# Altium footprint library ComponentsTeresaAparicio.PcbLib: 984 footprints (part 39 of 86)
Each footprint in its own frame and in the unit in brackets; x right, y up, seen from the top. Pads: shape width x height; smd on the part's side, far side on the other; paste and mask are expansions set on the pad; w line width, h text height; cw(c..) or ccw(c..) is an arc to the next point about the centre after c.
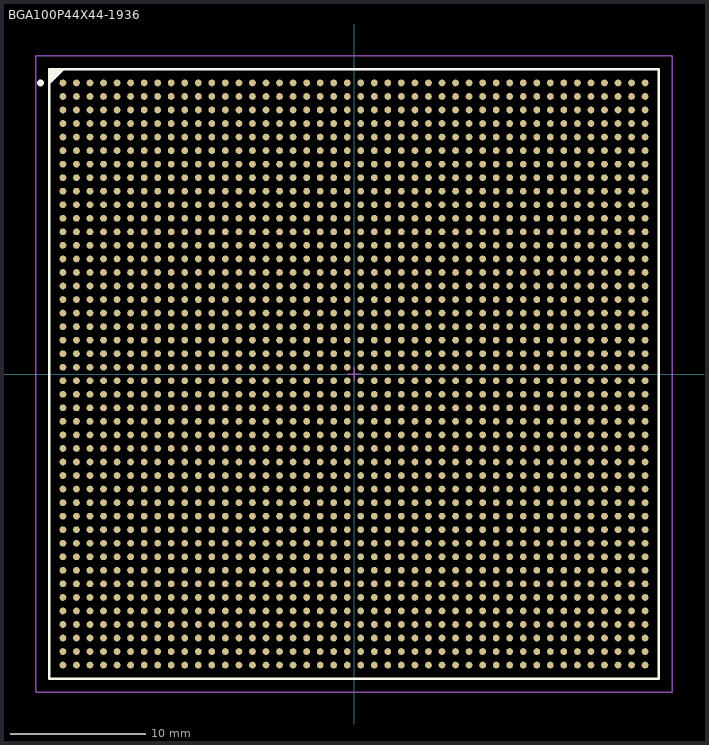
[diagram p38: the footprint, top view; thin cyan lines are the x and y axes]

## BGA100P44X44-1936 [mm] "BGA, 1936-Leads, Body 45x45mm, Pitch 1mm"
height 3.5
pads (1936):
  round 0.5 smd: A1(-21.5,21.5) A2(-20.5,21.5) A3(-19.5,21.5) A4(-18.5,21.5) A5(-17.5,21.5) A6(-16.5,21.5) A7(-15.5,21.5) A8(-14.5,21.5) A9(-13.5,21.5) A10(-12.5,21.5) A11(-11.5,21.5) A12(-10.5,21.5) A13(-9.5,21.5) A14(-8.5,21.5) A15(-7.5,21.5) A16(-6.5,21.5) A17(-5.5,21.5) A18(-4.5,21.5) A19(-3.5,21.5) A20(-2.5,21.5) A21(-1.5,21.5) A22(-0.5,21.5) A23(0.5,21.5) A24(1.5,21.5) A25(2.5,21.5) A26(3.5,21.5) A27(4.5,21.5) A28(5.5,21.5) A29(6.5,21.5) A30(7.5,21.5) A31(8.5,21.5) A32(9.5,21.5) A33(10.5,21.5) A34(11.5,21.5) A35(12.5,21.5) A36(13.5,21.5) A37(14.5,21.5) A38(15.5,21.5) A39(16.5,21.5) A40(17.5,21.5) A41(18.5,21.5) A42(19.5,21.5) A43(20.5,21.5) A44(21.5,21.5) AA1(-21.5,1.5) AA2(-20.5,1.5) AA3(-19.5,1.5) AA4(-18.5,1.5) AA5(-17.5,1.5) AA6(-16.5,1.5) AA7(-15.5,1.5) AA8(-14.5,1.5) AA9(-13.5,1.5) AA10(-12.5,1.5) AA11(-11.5,1.5) AA12(-10.5,1.5) AA13(-9.5,1.5) AA14(-8.5,1.5) AA15(-7.5,1.5) AA16(-6.5,1.5) AA17(-5.5,1.5) AA18(-4.5,1.5) AA19(-3.5,1.5) AA20(-2.5,1.5) AA21(-1.5,1.5) AA22(-0.5,1.5) AA23(0.5,1.5) AA24(1.5,1.5) AA25(2.5,1.5) AA26(3.5,1.5) AA27(4.5,1.5) AA28(5.5,1.5) AA29(6.5,1.5) AA30(7.5,1.5) AA31(8.5,1.5) AA32(9.5,1.5) AA33(10.5,1.5) AA34(11.5,1.5) AA35(12.5,1.5) AA36(13.5,1.5) AA37(14.5,1.5) AA38(15.5,1.5) AA39(16.5,1.5) AA40(17.5,1.5) AA41(18.5,1.5) AA42(19.5,1.5) AA43(20.5,1.5) AA44(21.5,1.5) AB1(-21.5,0.5) AB2(-20.5,0.5) AB3(-19.5,0.5) AB4(-18.5,0.5) AB5(-17.5,0.5) AB6(-16.5,0.5) AB7(-15.5,0.5) AB8(-14.5,0.5) AB9(-13.5,0.5) AB10(-12.5,0.5) AB11(-11.5,0.5) AB12(-10.5,0.5) AB13(-9.5,0.5) AB14(-8.5,0.5) AB15(-7.5,0.5) AB16(-6.5,0.5) AB17(-5.5,0.5) AB18(-4.5,0.5) AB19(-3.5,0.5) AB20(-2.5,0.5) AB21(-1.5,0.5) AB22(-0.5,0.5) AB23(0.5,0.5) AB24(1.5,0.5) AB25(2.5,0.5) AB26(3.5,0.5) AB27(4.5,0.5) AB28(5.5,0.5) AB29(6.5,0.5) AB30(7.5,0.5) AB31(8.5,0.5) AB32(9.5,0.5) AB33(10.5,0.5) AB34(11.5,0.5) AB35(12.5,0.5) AB36(13.5,0.5) AB37(14.5,0.5) AB38(15.5,0.5) AB39(16.5,0.5) AB40(17.5,0.5) AB41(18.5,0.5) AB42(19.5,0.5) AB43(20.5,0.5) AB44(21.5,0.5) AC1(-21.5,-0.5) AC2(-20.5,-0.5) AC3(-19.5,-0.5) AC4(-18.5,-0.5) AC5(-17.5,-0.5) AC6(-16.5,-0.5) AC7(-15.5,-0.5) AC8(-14.5,-0.5) AC9(-13.5,-0.5) AC10(-12.5,-0.5) AC11(-11.5,-0.5) AC12(-10.5,-0.5) AC13(-9.5,-0.5) AC14(-8.5,-0.5) AC15(-7.5,-0.5) AC16(-6.5,-0.5) AC17(-5.5,-0.5) AC18(-4.5,-0.5) AC19(-3.5,-0.5) AC20(-2.5,-0.5) AC21(-1.5,-0.5) AC22(-0.5,-0.5) AC23(0.5,-0.5) AC24(1.5,-0.5) AC25(2.5,-0.5) AC26(3.5,-0.5) AC27(4.5,-0.5) AC28(5.5,-0.5) AC29(6.5,-0.5) AC30(7.5,-0.5) AC31(8.5,-0.5) AC32(9.5,-0.5) AC33(10.5,-0.5) AC34(11.5,-0.5) AC35(12.5,-0.5) AC36(13.5,-0.5) AC37(14.5,-0.5) AC38(15.5,-0.5) AC39(16.5,-0.5) AC40(17.5,-0.5) AC41(18.5,-0.5) AC42(19.5,-0.5) AC43(20.5,-0.5) AC44(21.5,-0.5) AD1(-21.5,-1.5) AD2(-20.5,-1.5) AD3(-19.5,-1.5) AD4(-18.5,-1.5) AD5(-17.5,-1.5) AD6(-16.5,-1.5) AD7(-15.5,-1.5) AD8(-14.5,-1.5) AD9(-13.5,-1.5) AD10(-12.5,-1.5) AD11(-11.5,-1.5) AD12(-10.5,-1.5) AD13(-9.5,-1.5) AD14(-8.5,-1.5) AD15(-7.5,-1.5) AD16(-6.5,-1.5) AD17(-5.5,-1.5) AD18(-4.5,-1.5) AD19(-3.5,-1.5) AD20(-2.5,-1.5) AD21(-1.5,-1.5) AD22(-0.5,-1.5) AD23(0.5,-1.5) AD24(1.5,-1.5) AD25(2.5,-1.5) AD26(3.5,-1.5) AD27(4.5,-1.5) AD28(5.5,-1.5) AD29(6.5,-1.5) AD30(7.5,-1.5) AD31(8.5,-1.5) AD32(9.5,-1.5) AD33(10.5,-1.5) AD34(11.5,-1.5) AD35(12.5,-1.5) AD36(13.5,-1.5) AD37(14.5,-1.5) AD38(15.5,-1.5) AD39(16.5,-1.5) AD40(17.5,-1.5) AD41(18.5,-1.5) AD42(19.5,-1.5) AD43(20.5,-1.5) AD44(21.5,-1.5) AE1(-21.5,-2.5) AE2(-20.5,-2.5) AE3(-19.5,-2.5) AE4(-18.5,-2.5) AE5(-17.5,-2.5) AE6(-16.5,-2.5) AE7(-15.5,-2.5) AE8(-14.5,-2.5) AE9(-13.5,-2.5) AE10(-12.5,-2.5) AE11(-11.5,-2.5) AE12(-10.5,-2.5) AE13(-9.5,-2.5) AE14(-8.5,-2.5) AE15(-7.5,-2.5) AE16(-6.5,-2.5) AE17(-5.5,-2.5) AE18(-4.5,-2.5) AE19(-3.5,-2.5) AE20(-2.5,-2.5) AE21(-1.5,-2.5) AE22(-0.5,-2.5) AE23(0.5,-2.5) AE24(1.5,-2.5) AE25(2.5,-2.5) AE26(3.5,-2.5) AE27(4.5,-2.5) AE28(5.5,-2.5) AE29(6.5,-2.5) AE30(7.5,-2.5) AE31(8.5,-2.5) AE32(9.5,-2.5) AE33(10.5,-2.5) AE34(11.5,-2.5) AE35(12.5,-2.5) AE36(13.5,-2.5) AE37(14.5,-2.5) AE38(15.5,-2.5) AE39(16.5,-2.5) AE40(17.5,-2.5) AE41(18.5,-2.5) AE42(19.5,-2.5) AE43(20.5,-2.5) AE44(21.5,-2.5) AF1(-21.5,-3.5) AF2(-20.5,-3.5) AF3(-19.5,-3.5) AF4(-18.5,-3.5) AF5(-17.5,-3.5) AF6(-16.5,-3.5) AF7(-15.5,-3.5) AF8(-14.5,-3.5) AF9(-13.5,-3.5) AF10(-12.5,-3.5) AF11(-11.5,-3.5) AF12(-10.5,-3.5) AF13(-9.5,-3.5) AF14(-8.5,-3.5) AF15(-7.5,-3.5) AF16(-6.5,-3.5) AF17(-5.5,-3.5) AF18(-4.5,-3.5) AF19(-3.5,-3.5) AF20(-2.5,-3.5) AF21(-1.5,-3.5) AF22(-0.5,-3.5) AF23(0.5,-3.5) AF24(1.5,-3.5) AF25(2.5,-3.5) AF26(3.5,-3.5) AF27(4.5,-3.5) AF28(5.5,-3.5) AF29(6.5,-3.5) AF30(7.5,-3.5) AF31(8.5,-3.5) AF32(9.5,-3.5) AF33(10.5,-3.5) AF34(11.5,-3.5) AF35(12.5,-3.5) AF36(13.5,-3.5) AF37(14.5,-3.5) AF38(15.5,-3.5) AF39(16.5,-3.5) AF40(17.5,-3.5) AF41(18.5,-3.5) AF42(19.5,-3.5) AF43(20.5,-3.5) AF44(21.5,-3.5) AG1(-21.5,-4.5) AG2(-20.5,-4.5) AG3(-19.5,-4.5) AG4(-18.5,-4.5) AG5(-17.5,-4.5) AG6(-16.5,-4.5) AG7(-15.5,-4.5) AG8(-14.5,-4.5) AG9(-13.5,-4.5) AG10(-12.5,-4.5) AG11(-11.5,-4.5) AG12(-10.5,-4.5) AG13(-9.5,-4.5) AG14(-8.5,-4.5) AG15(-7.5,-4.5) AG16(-6.5,-4.5) AG17(-5.5,-4.5) AG18(-4.5,-4.5) AG19(-3.5,-4.5) AG20(-2.5,-4.5) AG21(-1.5,-4.5) AG22(-0.5,-4.5) AG23(0.5,-4.5) AG24(1.5,-4.5) AG25(2.5,-4.5) AG26(3.5,-4.5) AG27(4.5,-4.5) AG28(5.5,-4.5) AG29(6.5,-4.5) AG30(7.5,-4.5) AG31(8.5,-4.5) AG32(9.5,-4.5) AG33(10.5,-4.5) AG34(11.5,-4.5) AG35(12.5,-4.5) AG36(13.5,-4.5) AG37(14.5,-4.5) AG38(15.5,-4.5) AG39(16.5,-4.5) AG40(17.5,-4.5) AG41(18.5,-4.5) AG42(19.5,-4.5) AG43(20.5,-4.5) AG44(21.5,-4.5) AH1(-21.5,-5.5) AH2(-20.5,-5.5) AH3(-19.5,-5.5) AH4(-18.5,-5.5) AH5(-17.5,-5.5) AH6(-16.5,-5.5) AH7(-15.5,-5.5) AH8(-14.5,-5.5) AH9(-13.5,-5.5) AH10(-12.5,-5.5) AH11(-11.5,-5.5) AH12(-10.5,-5.5) AH13(-9.5,-5.5) AH14(-8.5,-5.5) AH15(-7.5,-5.5) AH16(-6.5,-5.5) AH17(-5.5,-5.5) AH18(-4.5,-5.5) AH19(-3.5,-5.5) AH20(-2.5,-5.5) AH21(-1.5,-5.5) AH22(-0.5,-5.5) AH23(0.5,-5.5) AH24(1.5,-5.5) AH25(2.5,-5.5) AH26(3.5,-5.5) AH27(4.5,-5.5) AH28(5.5,-5.5) AH29(6.5,-5.5) AH30(7.5,-5.5) AH31(8.5,-5.5) AH32(9.5,-5.5) AH33(10.5,-5.5) AH34(11.5,-5.5) AH35(12.5,-5.5) AH36(13.5,-5.5) AH37(14.5,-5.5) AH38(15.5,-5.5) AH39(16.5,-5.5) AH40(17.5,-5.5) AH41(18.5,-5.5) AH42(19.5,-5.5) AH43(20.5,-5.5) AH44(21.5,-5.5) AJ1(-21.5,-6.5) AJ2(-20.5,-6.5) AJ3(-19.5,-6.5) AJ4(-18.5,-6.5) AJ5(-17.5,-6.5) AJ6(-16.5,-6.5) AJ7(-15.5,-6.5) AJ8(-14.5,-6.5) AJ9(-13.5,-6.5) AJ10(-12.5,-6.5) AJ11(-11.5,-6.5) AJ12(-10.5,-6.5) AJ13(-9.5,-6.5) AJ14(-8.5,-6.5) AJ15(-7.5,-6.5) AJ16(-6.5,-6.5) AJ17(-5.5,-6.5) AJ18(-4.5,-6.5) AJ19(-3.5,-6.5) AJ20(-2.5,-6.5) AJ21(-1.5,-6.5) AJ22(-0.5,-6.5) AJ23(0.5,-6.5) AJ24(1.5,-6.5) AJ25(2.5,-6.5) AJ26(3.5,-6.5) AJ27(4.5,-6.5) AJ28(5.5,-6.5) AJ29(6.5,-6.5) AJ30(7.5,-6.5) AJ31(8.5,-6.5) AJ32(9.5,-6.5) AJ33(10.5,-6.5) AJ34(11.5,-6.5) AJ35(12.5,-6.5) AJ36(13.5,-6.5) AJ37(14.5,-6.5) AJ38(15.5,-6.5) AJ39(16.5,-6.5) AJ40(17.5,-6.5) AJ41(18.5,-6.5) AJ42(19.5,-6.5) AJ43(20.5,-6.5) AJ44(21.5,-6.5) AK1(-21.5,-7.5) AK2(-20.5,-7.5) AK3(-19.5,-7.5) AK4(-18.5,-7.5) AK5(-17.5,-7.5) AK6(-16.5,-7.5) AK7(-15.5,-7.5) AK8(-14.5,-7.5) AK9(-13.5,-7.5) AK10(-12.5,-7.5) AK11(-11.5,-7.5) AK12(-10.5,-7.5) AK13(-9.5,-7.5) AK14(-8.5,-7.5) AK15(-7.5,-7.5) AK16(-6.5,-7.5) AK17(-5.5,-7.5) AK18(-4.5,-7.5) AK19(-3.5,-7.5) AK20(-2.5,-7.5) AK21(-1.5,-7.5) AK22(-0.5,-7.5) AK23(0.5,-7.5) AK24(1.5,-7.5) AK25(2.5,-7.5) AK26(3.5,-7.5) AK27(4.5,-7.5) AK28(5.5,-7.5) AK29(6.5,-7.5) AK30(7.5,-7.5) AK31(8.5,-7.5) AK32(9.5,-7.5) AK33(10.5,-7.5) AK34(11.5,-7.5) AK35(12.5,-7.5) AK36(13.5,-7.5) AK37(14.5,-7.5) AK38(15.5,-7.5) AK39(16.5,-7.5) AK40(17.5,-7.5) AK41(18.5,-7.5) AK42(19.5,-7.5) AK43(20.5,-7.5) AK44(21.5,-7.5) AL1(-21.5,-8.5) AL2(-20.5,-8.5) AL3(-19.5,-8.5) AL4(-18.5,-8.5) AL5(-17.5,-8.5) AL6(-16.5,-8.5) AL7(-15.5,-8.5) AL8(-14.5,-8.5) AL9(-13.5,-8.5) AL10(-12.5,-8.5) AL11(-11.5,-8.5) AL12(-10.5,-8.5) AL13(-9.5,-8.5) AL14(-8.5,-8.5) AL15(-7.5,-8.5) AL16(-6.5,-8.5) AL17(-5.5,-8.5) AL18(-4.5,-8.5) AL19(-3.5,-8.5) AL20(-2.5,-8.5) AL21(-1.5,-8.5) AL22(-0.5,-8.5) AL23(0.5,-8.5) AL24(1.5,-8.5) AL25(2.5,-8.5) AL26(3.5,-8.5) AL27(4.5,-8.5) AL28(5.5,-8.5) AL29(6.5,-8.5) AL30(7.5,-8.5) AL31(8.5,-8.5) AL32(9.5,-8.5) AL33(10.5,-8.5) AL34(11.5,-8.5) AL35(12.5,-8.5) AL36(13.5,-8.5) AL37(14.5,-8.5) AL38(15.5,-8.5) AL39(16.5,-8.5) AL40(17.5,-8.5) AL41(18.5,-8.5) AL42(19.5,-8.5) AL43(20.5,-8.5) AL44(21.5,-8.5) AM1(-21.5,-9.5) AM2(-20.5,-9.5) AM3(-19.5,-9.5) AM4(-18.5,-9.5) AM5(-17.5,-9.5) AM6(-16.5,-9.5) AM7(-15.5,-9.5) AM8(-14.5,-9.5) AM9(-13.5,-9.5) AM10(-12.5,-9.5) AM11(-11.5,-9.5) AM12(-10.5,-9.5) AM13(-9.5,-9.5) AM14(-8.5,-9.5) AM15(-7.5,-9.5) AM16(-6.5,-9.5) AM17(-5.5,-9.5) AM18(-4.5,-9.5) AM19(-3.5,-9.5) AM20(-2.5,-9.5) AM21(-1.5,-9.5) AM22(-0.5,-9.5) AM23(0.5,-9.5) AM24(1.5,-9.5) AM25(2.5,-9.5) AM26(3.5,-9.5) AM27(4.5,-9.5) AM28(5.5,-9.5) AM29(6.5,-9.5) AM30(7.5,-9.5) AM31(8.5,-9.5) AM32(9.5,-9.5) AM33(10.5,-9.5) AM34(11.5,-9.5) AM35(12.5,-9.5) AM36(13.5,-9.5) AM37(14.5,-9.5) AM38(15.5,-9.5) AM39(16.5,-9.5) AM40(17.5,-9.5) AM41(18.5,-9.5) AM42(19.5,-9.5) AM43(20.5,-9.5) AM44(21.5,-9.5) AN1(-21.5,-10.5) AN2(-20.5,-10.5) AN3(-19.5,-10.5) AN4(-18.5,-10.5) AN5(-17.5,-10.5) AN6(-16.5,-10.5) AN7(-15.5,-10.5) AN8(-14.5,-10.5) AN9(-13.5,-10.5) AN10(-12.5,-10.5) AN11(-11.5,-10.5) AN12(-10.5,-10.5) AN13(-9.5,-10.5) AN14(-8.5,-10.5) AN15(-7.5,-10.5) AN16(-6.5,-10.5) AN17(-5.5,-10.5) AN18(-4.5,-10.5) AN19(-3.5,-10.5) AN20(-2.5,-10.5) AN21(-1.5,-10.5) AN22(-0.5,-10.5) AN23(0.5,-10.5) AN24(1.5,-10.5) AN25(2.5,-10.5) AN26(3.5,-10.5) AN27(4.5,-10.5) AN28(5.5,-10.5) AN29(6.5,-10.5) AN30(7.5,-10.5) AN31(8.5,-10.5) AN32(9.5,-10.5) AN33(10.5,-10.5) AN34(11.5,-10.5) AN35(12.5,-10.5) AN36(13.5,-10.5) AN37(14.5,-10.5) AN38(15.5,-10.5) AN39(16.5,-10.5) AN40(17.5,-10.5) AN41(18.5,-10.5) AN42(19.5,-10.5) AN43(20.5,-10.5) AN44(21.5,-10.5) AP1(-21.5,-11.5) AP2(-20.5,-11.5) AP3(-19.5,-11.5) AP4(-18.5,-11.5) AP5(-17.5,-11.5) AP6(-16.5,-11.5) AP7(-15.5,-11.5) AP8(-14.5,-11.5) AP9(-13.5,-11.5) AP10(-12.5,-11.5) AP11(-11.5,-11.5) AP12(-10.5,-11.5) AP13(-9.5,-11.5) AP14(-8.5,-11.5) AP15(-7.5,-11.5) AP16(-6.5,-11.5) AP17(-5.5,-11.5) AP18(-4.5,-11.5) AP19(-3.5,-11.5) AP20(-2.5,-11.5) AP21(-1.5,-11.5) AP22(-0.5,-11.5) AP23(0.5,-11.5) AP24(1.5,-11.5) AP25(2.5,-11.5) AP26(3.5,-11.5) AP27(4.5,-11.5) AP28(5.5,-11.5) AP29(6.5,-11.5) AP30(7.5,-11.5) AP31(8.5,-11.5) AP32(9.5,-11.5) AP33(10.5,-11.5) AP34(11.5,-11.5) AP35(12.5,-11.5) AP36(13.5,-11.5) AP37(14.5,-11.5) AP38(15.5,-11.5) AP39(16.5,-11.5) AP40(17.5,-11.5) AP41(18.5,-11.5) AP42(19.5,-11.5) AP43(20.5,-11.5) AP44(21.5,-11.5) AR1(-21.5,-12.5) AR2(-20.5,-12.5) AR3(-19.5,-12.5) AR4(-18.5,-12.5) AR5(-17.5,-12.5) AR6(-16.5,-12.5) AR7(-15.5,-12.5) AR8(-14.5,-12.5) AR9(-13.5,-12.5) AR10(-12.5,-12.5) AR11(-11.5,-12.5) AR12(-10.5,-12.5) AR13(-9.5,-12.5) AR14(-8.5,-12.5) AR15(-7.5,-12.5) AR16(-6.5,-12.5) AR17(-5.5,-12.5) AR18(-4.5,-12.5) AR19(-3.5,-12.5) AR20(-2.5,-12.5) AR21(-1.5,-12.5) AR22(-0.5,-12.5) AR23(0.5,-12.5) AR24(1.5,-12.5) AR25(2.5,-12.5) AR26(3.5,-12.5) AR27(4.5,-12.5) AR28(5.5,-12.5) AR29(6.5,-12.5) AR30(7.5,-12.5) AR31(8.5,-12.5) AR32(9.5,-12.5) AR33(10.5,-12.5) AR34(11.5,-12.5) AR35(12.5,-12.5) AR36(13.5,-12.5) AR37(14.5,-12.5) AR38(15.5,-12.5) AR39(16.5,-12.5) AR40(17.5,-12.5) AR41(18.5,-12.5) AR42(19.5,-12.5) AR43(20.5,-12.5) AR44(21.5,-12.5) AT1(-21.5,-13.5) AT2(-20.5,-13.5) AT3(-19.5,-13.5) AT4(-18.5,-13.5) AT5(-17.5,-13.5) AT6(-16.5,-13.5) AT7(-15.5,-13.5) AT8(-14.5,-13.5) AT9(-13.5,-13.5) AT10(-12.5,-13.5) AT11(-11.5,-13.5) AT12(-10.5,-13.5) AT13(-9.5,-13.5) AT14(-8.5,-13.5) AT15(-7.5,-13.5) AT16(-6.5,-13.5) AT17(-5.5,-13.5) AT18(-4.5,-13.5) AT19(-3.5,-13.5) AT20(-2.5,-13.5) AT21(-1.5,-13.5) AT22(-0.5,-13.5) AT23(0.5,-13.5) AT24(1.5,-13.5) AT25(2.5,-13.5) AT26(3.5,-13.5) AT27(4.5,-13.5) AT28(5.5,-13.5) AT29(6.5,-13.5) AT30(7.5,-13.5) AT31(8.5,-13.5) AT32(9.5,-13.5) AT33(10.5,-13.5) AT34(11.5,-13.5) AT35(12.5,-13.5) AT36(13.5,-13.5) AT37(14.5,-13.5) AT38(15.5,-13.5) AT39(16.5,-13.5) AT40(17.5,-13.5) AT41(18.5,-13.5) AT42(19.5,-13.5) AT43(20.5,-13.5) AT44(21.5,-13.5) AU1(-21.5,-14.5) AU2(-20.5,-14.5) AU3(-19.5,-14.5) AU4(-18.5,-14.5) AU5(-17.5,-14.5) AU6(-16.5,-14.5) AU7(-15.5,-14.5) AU8(-14.5,-14.5) AU9(-13.5,-14.5) AU10(-12.5,-14.5) AU11(-11.5,-14.5) AU12(-10.5,-14.5) AU13(-9.5,-14.5) AU14(-8.5,-14.5) AU15(-7.5,-14.5) AU16(-6.5,-14.5) AU17(-5.5,-14.5) AU18(-4.5,-14.5) AU19(-3.5,-14.5) AU20(-2.5,-14.5) AU21(-1.5,-14.5) AU22(-0.5,-14.5) AU23(0.5,-14.5) AU24(1.5,-14.5) AU25(2.5,-14.5) AU26(3.5,-14.5) AU27(4.5,-14.5) AU28(5.5,-14.5) AU29(6.5,-14.5) AU30(7.5,-14.5) AU31(8.5,-14.5) AU32(9.5,-14.5) AU33(10.5,-14.5) AU34(11.5,-14.5) AU35(12.5,-14.5) AU36(13.5,-14.5) AU37(14.5,-14.5) AU38(15.5,-14.5) AU39(16.5,-14.5) AU40(17.5,-14.5) AU41(18.5,-14.5) AU42(19.5,-14.5) AU43(20.5,-14.5) AU44(21.5,-14.5) AV1(-21.5,-15.5) AV2(-20.5,-15.5) AV3(-19.5,-15.5) AV4(-18.5,-15.5) AV5(-17.5,-15.5) AV6(-16.5,-15.5) AV7(-15.5,-15.5) AV8(-14.5,-15.5) AV9(-13.5,-15.5) AV10(-12.5,-15.5) AV11(-11.5,-15.5) AV12(-10.5,-15.5) AV13(-9.5,-15.5) AV14(-8.5,-15.5) AV15(-7.5,-15.5) AV16(-6.5,-15.5) AV17(-5.5,-15.5) AV18(-4.5,-15.5) AV19(-3.5,-15.5) AV20(-2.5,-15.5) AV21(-1.5,-15.5) AV22(-0.5,-15.5) AV23(0.5,-15.5) AV24(1.5,-15.5) AV25(2.5,-15.5) AV26(3.5,-15.5) AV27(4.5,-15.5) AV28(5.5,-15.5) AV29(6.5,-15.5) AV30(7.5,-15.5) AV31(8.5,-15.5) AV32(9.5,-15.5) AV33(10.5,-15.5) AV34(11.5,-15.5) AV35(12.5,-15.5) AV36(13.5,-15.5) AV37(14.5,-15.5) AV38(15.5,-15.5) AV39(16.5,-15.5) AV40(17.5,-15.5) AV41(18.5,-15.5) AV42(19.5,-15.5) AV43(20.5,-15.5) AV44(21.5,-15.5) AW1(-21.5,-16.5) AW2(-20.5,-16.5) AW3(-19.5,-16.5) AW4(-18.5,-16.5) AW5(-17.5,-16.5) AW6(-16.5,-16.5) AW7(-15.5,-16.5) AW8(-14.5,-16.5) AW9(-13.5,-16.5) AW10(-12.5,-16.5) AW11(-11.5,-16.5) AW12(-10.5,-16.5) AW13(-9.5,-16.5) AW14(-8.5,-16.5) AW15(-7.5,-16.5) AW16(-6.5,-16.5) AW17(-5.5,-16.5) AW18(-4.5,-16.5) AW19(-3.5,-16.5) AW20(-2.5,-16.5) AW21(-1.5,-16.5) AW22(-0.5,-16.5) AW23(0.5,-16.5) AW24(1.5,-16.5) AW25(2.5,-16.5) AW26(3.5,-16.5) AW27(4.5,-16.5) AW28(5.5,-16.5) AW29(6.5,-16.5) AW30(7.5,-16.5) AW31(8.5,-16.5) AW32(9.5,-16.5) AW33(10.5,-16.5) AW34(11.5,-16.5) AW35(12.5,-16.5) AW36(13.5,-16.5) AW37(14.5,-16.5) AW38(15.5,-16.5) AW39(16.5,-16.5) AW40(17.5,-16.5) AW41(18.5,-16.5) AW42(19.5,-16.5) AW43(20.5,-16.5) AW44(21.5,-16.5) AY1(-21.5,-17.5) AY2(-20.5,-17.5) AY3(-19.5,-17.5) AY4(-18.5,-17.5) AY5(-17.5,-17.5) AY6(-16.5,-17.5) AY7(-15.5,-17.5) AY8(-14.5,-17.5) AY9(-13.5,-17.5) AY10(-12.5,-17.5) AY11(-11.5,-17.5) AY12(-10.5,-17.5) AY13(-9.5,-17.5) AY14(-8.5,-17.5) AY15(-7.5,-17.5) AY16(-6.5,-17.5) AY17(-5.5,-17.5) AY18(-4.5,-17.5) AY19(-3.5,-17.5) AY20(-2.5,-17.5) AY21(-1.5,-17.5) AY22(-0.5,-17.5) AY23(0.5,-17.5) AY24(1.5,-17.5) AY25(2.5,-17.5) AY26(3.5,-17.5) AY27(4.5,-17.5) AY28(5.5,-17.5) AY29(6.5,-17.5) AY30(7.5,-17.5) AY31(8.5,-17.5) AY32(9.5,-17.5) AY33(10.5,-17.5) AY34(11.5,-17.5) AY35(12.5,-17.5) AY36(13.5,-17.5) AY37(14.5,-17.5) AY38(15.5,-17.5) AY39(16.5,-17.5) AY40(17.5,-17.5) AY41(18.5,-17.5) AY42(19.5,-17.5) AY43(20.5,-17.5) AY44(21.5,-17.5) B1(-21.5,20.5) B2(-20.5,20.5) B3(-19.5,20.5) B4(-18.5,20.5) B5(-17.5,20.5) B6(-16.5,20.5) B7(-15.5,20.5) B8(-14.5,20.5) B9(-13.5,20.5) B10(-12.5,20.5) B11(-11.5,20.5) B12(-10.5,20.5) B13(-9.5,20.5) B14(-8.5,20.5) B15(-7.5,20.5) B16(-6.5,20.5) B17(-5.5,20.5) B18(-4.5,20.5) B19(-3.5,20.5) B20(-2.5,20.5) B21(-1.5,20.5) B22(-0.5,20.5) B23(0.5,20.5) B24(1.5,20.5) B25(2.5,20.5) B26(3.5,20.5) B27(4.5,20.5) B28(5.5,20.5) B29(6.5,20.5) B30(7.5,20.5) B31(8.5,20.5) B32(9.5,20.5) B33(10.5,20.5) B34(11.5,20.5) B35(12.5,20.5) B36(13.5,20.5) B37(14.5,20.5) B38(15.5,20.5) B39(16.5,20.5) B40(17.5,20.5) B41(18.5,20.5) B42(19.5,20.5) B43(20.5,20.5) B44(21.5,20.5) BA1(-21.5,-18.5) BA2(-20.5,-18.5) BA3(-19.5,-18.5) BA4(-18.5,-18.5) BA5(-17.5,-18.5) BA6(-16.5,-18.5) BA7(-15.5,-18.5) BA8(-14.5,-18.5) BA9(-13.5,-18.5) BA10(-12.5,-18.5) BA11(-11.5,-18.5) BA12(-10.5,-18.5) BA13(-9.5,-18.5) BA14(-8.5,-18.5) BA15(-7.5,-18.5) BA16(-6.5,-18.5) BA17(-5.5,-18.5) BA18(-4.5,-18.5) BA19(-3.5,-18.5) BA20(-2.5,-18.5) BA21(-1.5,-18.5) BA22(-0.5,-18.5) BA23(0.5,-18.5) BA24(1.5,-18.5) BA25(2.5,-18.5) BA26(3.5,-18.5) BA27(4.5,-18.5) BA28(5.5,-18.5) BA29(6.5,-18.5) BA30(7.5,-18.5) BA31(8.5,-18.5) BA32(9.5,-18.5) BA33(10.5,-18.5) BA34(11.5,-18.5) BA35(12.5,-18.5) BA36(13.5,-18.5) BA37(14.5,-18.5) BA38(15.5,-18.5) BA39(16.5,-18.5) BA40(17.5,-18.5) BA41(18.5,-18.5) BA42(19.5,-18.5) BA43(20.5,-18.5) BA44(21.5,-18.5) BB1(-21.5,-19.5) BB2(-20.5,-19.5) BB3(-19.5,-19.5) BB4(-18.5,-19.5) BB5(-17.5,-19.5) BB6(-16.5,-19.5) BB7(-15.5,-19.5) BB8(-14.5,-19.5) BB9(-13.5,-19.5) BB10(-12.5,-19.5) BB11(-11.5,-19.5) BB12(-10.5,-19.5) BB13(-9.5,-19.5) BB14(-8.5,-19.5) BB15(-7.5,-19.5) BB16(-6.5,-19.5) BB17(-5.5,-19.5) BB18(-4.5,-19.5) BB19(-3.5,-19.5) BB20(-2.5,-19.5) BB21(-1.5,-19.5) BB22(-0.5,-19.5) BB23(0.5,-19.5) BB24(1.5,-19.5) BB25(2.5,-19.5) BB26(3.5,-19.5) BB27(4.5,-19.5) BB28(5.5,-19.5) BB29(6.5,-19.5) BB30(7.5,-19.5) BB31(8.5,-19.5) BB32(9.5,-19.5) BB33(10.5,-19.5) BB34(11.5,-19.5) BB35(12.5,-19.5) BB36(13.5,-19.5) BB37(14.5,-19.5) BB38(15.5,-19.5) BB39(16.5,-19.5) BB40(17.5,-19.5) BB41(18.5,-19.5) BB42(19.5,-19.5) BB43(20.5,-19.5) BB44(21.5,-19.5) BC1(-21.5,-20.5) BC2(-20.5,-20.5) BC3(-19.5,-20.5) BC4(-18.5,-20.5) BC5(-17.5,-20.5) BC6(-16.5,-20.5) BC7(-15.5,-20.5) BC8(-14.5,-20.5) BC9(-13.5,-20.5) BC10(-12.5,-20.5) BC11(-11.5,-20.5) BC12(-10.5,-20.5) BC13(-9.5,-20.5) BC14(-8.5,-20.5) BC15(-7.5,-20.5) BC16(-6.5,-20.5) BC17(-5.5,-20.5) BC18(-4.5,-20.5) BC19(-3.5,-20.5) BC20(-2.5,-20.5) BC21(-1.5,-20.5) BC22(-0.5,-20.5) BC23(0.5,-20.5) BC24(1.5,-20.5) BC25(2.5,-20.5) BC26(3.5,-20.5) BC27(4.5,-20.5) BC28(5.5,-20.5) BC29(6.5,-20.5) BC30(7.5,-20.5) BC31(8.5,-20.5) BC32(9.5,-20.5) BC33(10.5,-20.5) BC34(11.5,-20.5) BC35(12.5,-20.5) BC36(13.5,-20.5) BC37(14.5,-20.5) BC38(15.5,-20.5) BC39(16.5,-20.5) BC40(17.5,-20.5) BC41(18.5,-20.5) BC42(19.5,-20.5) BC43(20.5,-20.5) BC44(21.5,-20.5) BD1(-21.5,-21.5) BD2(-20.5,-21.5) BD3(-19.5,-21.5) BD4(-18.5,-21.5) BD5(-17.5,-21.5) BD6(-16.5,-21.5) BD7(-15.5,-21.5) BD8(-14.5,-21.5) BD9(-13.5,-21.5) BD10(-12.5,-21.5) BD11(-11.5,-21.5) BD12(-10.5,-21.5) BD13(-9.5,-21.5) BD14(-8.5,-21.5) BD15(-7.5,-21.5) BD16(-6.5,-21.5) BD17(-5.5,-21.5) BD18(-4.5,-21.5) BD19(-3.5,-21.5) BD20(-2.5,-21.5) BD21(-1.5,-21.5) BD22(-0.5,-21.5) BD23(0.5,-21.5) BD24(1.5,-21.5) BD25(2.5,-21.5) BD26(3.5,-21.5) BD27(4.5,-21.5) BD28(5.5,-21.5) BD29(6.5,-21.5) BD30(7.5,-21.5) BD31(8.5,-21.5) BD32(9.5,-21.5) BD33(10.5,-21.5) BD34(11.5,-21.5) BD35(12.5,-21.5) BD36(13.5,-21.5) BD37(14.5,-21.5) BD38(15.5,-21.5) BD39(16.5,-21.5) BD40(17.5,-21.5) BD41(18.5,-21.5) BD42(19.5,-21.5) BD43(20.5,-21.5) BD44(21.5,-21.5) C1(-21.5,19.5) C2(-20.5,19.5) C3(-19.5,19.5) C4(-18.5,19.5) C5(-17.5,19.5) C6(-16.5,19.5) C7(-15.5,19.5) C8(-14.5,19.5) C9(-13.5,19.5) C10(-12.5,19.5) C11(-11.5,19.5) C12(-10.5,19.5) C13(-9.5,19.5) C14(-8.5,19.5) C15(-7.5,19.5) C16(-6.5,19.5) C17(-5.5,19.5) C18(-4.5,19.5) C19(-3.5,19.5) C20(-2.5,19.5) C21(-1.5,19.5) C22(-0.5,19.5) C23(0.5,19.5) C24(1.5,19.5) C25(2.5,19.5) C26(3.5,19.5) C27(4.5,19.5) C28(5.5,19.5) C29(6.5,19.5) C30(7.5,19.5) C31(8.5,19.5) C32(9.5,19.5) C33(10.5,19.5) C34(11.5,19.5) C35(12.5,19.5) C36(13.5,19.5) C37(14.5,19.5) C38(15.5,19.5) C39(16.5,19.5) C40(17.5,19.5) C41(18.5,19.5) C42(19.5,19.5) C43(20.5,19.5) C44(21.5,19.5) D1(-21.5,18.5) D2(-20.5,18.5) D3(-19.5,18.5) D4(-18.5,18.5) D5(-17.5,18.5) D6(-16.5,18.5) D7(-15.5,18.5) D8(-14.5,18.5) D9(-13.5,18.5) D10(-12.5,18.5) D11(-11.5,18.5) D12(-10.5,18.5) D13(-9.5,18.5) D14(-8.5,18.5) D15(-7.5,18.5) D16(-6.5,18.5) D17(-5.5,18.5) D18(-4.5,18.5) D19(-3.5,18.5) D20(-2.5,18.5) D21(-1.5,18.5) D22(-0.5,18.5) D23(0.5,18.5) D24(1.5,18.5) D25(2.5,18.5) D26(3.5,18.5) D27(4.5,18.5) D28(5.5,18.5) D29(6.5,18.5) D30(7.5,18.5) D31(8.5,18.5) D32(9.5,18.5) D33(10.5,18.5) D34(11.5,18.5) D35(12.5,18.5) D36(13.5,18.5) D37(14.5,18.5) D38(15.5,18.5) D39(16.5,18.5) D40(17.5,18.5) D41(18.5,18.5) D42(19.5,18.5) D43(20.5,18.5) D44(21.5,18.5) E1(-21.5,17.5) E2(-20.5,17.5) E3(-19.5,17.5) E4(-18.5,17.5) E5(-17.5,17.5) E6(-16.5,17.5) E7(-15.5,17.5) E8(-14.5,17.5) E9(-13.5,17.5) E10(-12.5,17.5) E11(-11.5,17.5) E12(-10.5,17.5) E13(-9.5,17.5) E14(-8.5,17.5) E15(-7.5,17.5) E16(-6.5,17.5) E17(-5.5,17.5) E18(-4.5,17.5) E19(-3.5,17.5) E20(-2.5,17.5) E21(-1.5,17.5) E22(-0.5,17.5) E23(0.5,17.5) E24(1.5,17.5) E25(2.5,17.5) E26(3.5,17.5) E27(4.5,17.5) E28(5.5,17.5) E29(6.5,17.5) E30(7.5,17.5) E31(8.5,17.5) E32(9.5,17.5) E33(10.5,17.5) E34(11.5,17.5) E35(12.5,17.5) E36(13.5,17.5) E37(14.5,17.5) E38(15.5,17.5) E39(16.5,17.5) E40(17.5,17.5) E41(18.5,17.5) E42(19.5,17.5) E43(20.5,17.5) E44(21.5,17.5) F1(-21.5,16.5) F2(-20.5,16.5) F3(-19.5,16.5) F4(-18.5,16.5) F5(-17.5,16.5) F6(-16.5,16.5) F7(-15.5,16.5) F8(-14.5,16.5) F9(-13.5,16.5) F10(-12.5,16.5) F11(-11.5,16.5) F12(-10.5,16.5) F13(-9.5,16.5) F14(-8.5,16.5) F15(-7.5,16.5) F16(-6.5,16.5) F17(-5.5,16.5) F18(-4.5,16.5) F19(-3.5,16.5) F20(-2.5,16.5) F21(-1.5,16.5) F22(-0.5,16.5) F23(0.5,16.5) F24(1.5,16.5) F25(2.5,16.5) F26(3.5,16.5) F27(4.5,16.5) F28(5.5,16.5) F29(6.5,16.5) F30(7.5,16.5) F31(8.5,16.5) F32(9.5,16.5) F33(10.5,16.5) F34(11.5,16.5) F35(12.5,16.5) F36(13.5,16.5) F37(14.5,16.5) F38(15.5,16.5) F39(16.5,16.5) F40(17.5,16.5) F41(18.5,16.5) F42(19.5,16.5) F43(20.5,16.5) F44(21.5,16.5) G1(-21.5,15.5) G2(-20.5,15.5) G3(-19.5,15.5) G4(-18.5,15.5) G5(-17.5,15.5) G6(-16.5,15.5) G7(-15.5,15.5) G8(-14.5,15.5) G9(-13.5,15.5) G10(-12.5,15.5) G11(-11.5,15.5) G12(-10.5,15.5) G13(-9.5,15.5) G14(-8.5,15.5) G15(-7.5,15.5) G16(-6.5,15.5) G17(-5.5,15.5) G18(-4.5,15.5) G19(-3.5,15.5) G20(-2.5,15.5) G21(-1.5,15.5) G22(-0.5,15.5) G23(0.5,15.5) G24(1.5,15.5) G25(2.5,15.5) G26(3.5,15.5) G27(4.5,15.5) G28(5.5,15.5) G29(6.5,15.5) G30(7.5,15.5) G31(8.5,15.5) G32(9.5,15.5) G33(10.5,15.5) G34(11.5,15.5) G35(12.5,15.5) G36(13.5,15.5) G37(14.5,15.5) G38(15.5,15.5) G39(16.5,15.5) G40(17.5,15.5) G41(18.5,15.5) G42(19.5,15.5) G43(20.5,15.5) G44(21.5,15.5) H1(-21.5,14.5) H2(-20.5,14.5) H3(-19.5,14.5) H4(-18.5,14.5) H5(-17.5,14.5) H6(-16.5,14.5) H7(-15.5,14.5) H8(-14.5,14.5) H9(-13.5,14.5) H10(-12.5,14.5) H11(-11.5,14.5) H12(-10.5,14.5) H13(-9.5,14.5) H14(-8.5,14.5) H15(-7.5,14.5) H16(-6.5,14.5) H17(-5.5,14.5) H18(-4.5,14.5) H19(-3.5,14.5) H20(-2.5,14.5) H21(-1.5,14.5) H22(-0.5,14.5) H23(0.5,14.5) H24(1.5,14.5) H25(2.5,14.5) H26(3.5,14.5) H27(4.5,14.5) H28(5.5,14.5) H29(6.5,14.5) H30(7.5,14.5) H31(8.5,14.5) H32(9.5,14.5) H33(10.5,14.5) H34(11.5,14.5) H35(12.5,14.5) H36(13.5,14.5) H37(14.5,14.5) H38(15.5,14.5) H39(16.5,14.5) H40(17.5,14.5) H41(18.5,14.5) H42(19.5,14.5) H43(20.5,14.5) H44(21.5,14.5) J1(-21.5,13.5) J2(-20.5,13.5) J3(-19.5,13.5) J4(-18.5,13.5) J5(-17.5,13.5) J6(-16.5,13.5) J7(-15.5,13.5) J8(-14.5,13.5) J9(-13.5,13.5) J10(-12.5,13.5) J11(-11.5,13.5) J12(-10.5,13.5) J13(-9.5,13.5) J14(-8.5,13.5) J15(-7.5,13.5) J16(-6.5,13.5) J17(-5.5,13.5) J18(-4.5,13.5) J19(-3.5,13.5) J20(-2.5,13.5) J21(-1.5,13.5) J22(-0.5,13.5) J23(0.5,13.5) J24(1.5,13.5) J25(2.5,13.5) J26(3.5,13.5) J27(4.5,13.5) J28(5.5,13.5) J29(6.5,13.5) J30(7.5,13.5) J31(8.5,13.5) J32(9.5,13.5) J33(10.5,13.5) J34(11.5,13.5) J35(12.5,13.5) J36(13.5,13.5) J37(14.5,13.5) J38(15.5,13.5) J39(16.5,13.5) J40(17.5,13.5) J41(18.5,13.5) J42(19.5,13.5) J43(20.5,13.5) J44(21.5,13.5) K1(-21.5,12.5) K2(-20.5,12.5) K3(-19.5,12.5) K4(-18.5,12.5) K5(-17.5,12.5) K6(-16.5,12.5) K7(-15.5,12.5) K8(-14.5,12.5) K9(-13.5,12.5) K10(-12.5,12.5) K11(-11.5,12.5) K12(-10.5,12.5) K13(-9.5,12.5) K14(-8.5,12.5) K15(-7.5,12.5) K16(-6.5,12.5) K17(-5.5,12.5) K18(-4.5,12.5) K19(-3.5,12.5) K20(-2.5,12.5) K21(-1.5,12.5) K22(-0.5,12.5) K23(0.5,12.5) K24(1.5,12.5) K25(2.5,12.5) K26(3.5,12.5) K27(4.5,12.5) K28(5.5,12.5) K29(6.5,12.5) K30(7.5,12.5) K31(8.5,12.5) K32(9.5,12.5) K33(10.5,12.5) K34(11.5,12.5) K35(12.5,12.5) K36(13.5,12.5) K37(14.5,12.5) K38(15.5,12.5) K39(16.5,12.5) K40(17.5,12.5) K41(18.5,12.5) K42(19.5,12.5) K43(20.5,12.5) K44(21.5,12.5) L1(-21.5,11.5) L2(-20.5,11.5) L3(-19.5,11.5) L4(-18.5,11.5) L5(-17.5,11.5) L6(-16.5,11.5) L7(-15.5,11.5) L8(-14.5,11.5) L9(-13.5,11.5) L10(-12.5,11.5) L11(-11.5,11.5) L12(-10.5,11.5) L13(-9.5,11.5) L14(-8.5,11.5) L15(-7.5,11.5) L16(-6.5,11.5) L17(-5.5,11.5) L18(-4.5,11.5) L19(-3.5,11.5) L20(-2.5,11.5) L21(-1.5,11.5) L22(-0.5,11.5) L23(0.5,11.5) L24(1.5,11.5) L25(2.5,11.5) L26(3.5,11.5) L27(4.5,11.5) L28(5.5,11.5) L29(6.5,11.5) L30(7.5,11.5) L31(8.5,11.5) L32(9.5,11.5) L33(10.5,11.5) L34(11.5,11.5) L35(12.5,11.5) L36(13.5,11.5) L37(14.5,11.5) L38(15.5,11.5) L39(16.5,11.5) L40(17.5,11.5) L41(18.5,11.5) L42(19.5,11.5) L43(20.5,11.5) L44(21.5,11.5) M1(-21.5,10.5) M2(-20.5,10.5) M3(-19.5,10.5) M4(-18.5,10.5) M5(-17.5,10.5) M6(-16.5,10.5) M7(-15.5,10.5) M8(-14.5,10.5) M9(-13.5,10.5) M10(-12.5,10.5) M11(-11.5,10.5) M12(-10.5,10.5) M13(-9.5,10.5) M14(-8.5,10.5) M15(-7.5,10.5) M16(-6.5,10.5) M17(-5.5,10.5) M18(-4.5,10.5) M19(-3.5,10.5) M20(-2.5,10.5) M21(-1.5,10.5) M22(-0.5,10.5) M23(0.5,10.5) M24(1.5,10.5) M25(2.5,10.5) M26(3.5,10.5) M27(4.5,10.5) M28(5.5,10.5) M29(6.5,10.5) M30(7.5,10.5) M31(8.5,10.5) M32(9.5,10.5) M33(10.5,10.5) M34(11.5,10.5) M35(12.5,10.5) M36(13.5,10.5) M37(14.5,10.5) M38(15.5,10.5) M39(16.5,10.5) M40(17.5,10.5) M41(18.5,10.5) M42(19.5,10.5) M43(20.5,10.5) M44(21.5,10.5) N1(-21.5,9.5) N2(-20.5,9.5) N3(-19.5,9.5) N4(-18.5,9.5) N5(-17.5,9.5) N6(-16.5,9.5) N7(-15.5,9.5) N8(-14.5,9.5) N9(-13.5,9.5) N10(-12.5,9.5) N11(-11.5,9.5) N12(-10.5,9.5) N13(-9.5,9.5) N14(-8.5,9.5) N15(-7.5,9.5) N16(-6.5,9.5) N17(-5.5,9.5) N18(-4.5,9.5) N19(-3.5,9.5) N20(-2.5,9.5) N21(-1.5,9.5) N22(-0.5,9.5) N23(0.5,9.5) N24(1.5,9.5) N25(2.5,9.5) N26(3.5,9.5) N27(4.5,9.5) N28(5.5,9.5) N29(6.5,9.5) N30(7.5,9.5) N31(8.5,9.5) N32(9.5,9.5) N33(10.5,9.5) N34(11.5,9.5) N35(12.5,9.5) N36(13.5,9.5) N37(14.5,9.5) N38(15.5,9.5) N39(16.5,9.5) N40(17.5,9.5) N41(18.5,9.5) N42(19.5,9.5) N43(20.5,9.5) N44(21.5,9.5) P1(-21.5,8.5) P2(-20.5,8.5) P3(-19.5,8.5) P4(-18.5,8.5) P5(-17.5,8.5) P6(-16.5,8.5) P7(-15.5,8.5) P8(-14.5,8.5) P9(-13.5,8.5) P10(-12.5,8.5) P11(-11.5,8.5) P12(-10.5,8.5) P13(-9.5,8.5) P14(-8.5,8.5) P15(-7.5,8.5) P16(-6.5,8.5) P17(-5.5,8.5) P18(-4.5,8.5) P19(-3.5,8.5) P20(-2.5,8.5) P21(-1.5,8.5) P22(-0.5,8.5) P23(0.5,8.5) P24(1.5,8.5) P25(2.5,8.5) P26(3.5,8.5) P27(4.5,8.5) P28(5.5,8.5) P29(6.5,8.5) P30(7.5,8.5) P31(8.5,8.5) P32(9.5,8.5) P33(10.5,8.5) P34(11.5,8.5) P35(12.5,8.5) P36(13.5,8.5) P37(14.5,8.5) P38(15.5,8.5) P39(16.5,8.5) P40(17.5,8.5) P41(18.5,8.5) P42(19.5,8.5) P43(20.5,8.5) P44(21.5,8.5) R1(-21.5,7.5) R2(-20.5,7.5) R3(-19.5,7.5) R4(-18.5,7.5) R5(-17.5,7.5) R6(-16.5,7.5) R7(-15.5,7.5) R8(-14.5,7.5) R9(-13.5,7.5) R10(-12.5,7.5) R11(-11.5,7.5) R12(-10.5,7.5) R13(-9.5,7.5) R14(-8.5,7.5) R15(-7.5,7.5) R16(-6.5,7.5) R17(-5.5,7.5) R18(-4.5,7.5) R19(-3.5,7.5) R20(-2.5,7.5) R21(-1.5,7.5) R22(-0.5,7.5) R23(0.5,7.5) R24(1.5,7.5) R25(2.5,7.5) R26(3.5,7.5) R27(4.5,7.5) R28(5.5,7.5) R29(6.5,7.5) R30(7.5,7.5) R31(8.5,7.5) R32(9.5,7.5) R33(10.5,7.5) R34(11.5,7.5) R35(12.5,7.5) R36(13.5,7.5) R37(14.5,7.5) R38(15.5,7.5) R39(16.5,7.5) R40(17.5,7.5) R41(18.5,7.5) R42(19.5,7.5) R43(20.5,7.5) R44(21.5,7.5) T1(-21.5,6.5) T2(-20.5,6.5) T3(-19.5,6.5) T4(-18.5,6.5) T5(-17.5,6.5) T6(-16.5,6.5) T7(-15.5,6.5) T8(-14.5,6.5) T9(-13.5,6.5) T10(-12.5,6.5) T11(-11.5,6.5) T12(-10.5,6.5) T13(-9.5,6.5) T14(-8.5,6.5) T15(-7.5,6.5) T16(-6.5,6.5) T17(-5.5,6.5) T18(-4.5,6.5) T19(-3.5,6.5) T20(-2.5,6.5) T21(-1.5,6.5) T22(-0.5,6.5) T23(0.5,6.5) T24(1.5,6.5) T25(2.5,6.5) T26(3.5,6.5) T27(4.5,6.5) T28(5.5,6.5) T29(6.5,6.5) T30(7.5,6.5) T31(8.5,6.5) T32(9.5,6.5) T33(10.5,6.5) T34(11.5,6.5) T35(12.5,6.5) T36(13.5,6.5) T37(14.5,6.5) T38(15.5,6.5) T39(16.5,6.5) T40(17.5,6.5) T41(18.5,6.5) T42(19.5,6.5) T43(20.5,6.5) T44(21.5,6.5) U1(-21.5,5.5) U2(-20.5,5.5) U3(-19.5,5.5) U4(-18.5,5.5) U5(-17.5,5.5) U6(-16.5,5.5) U7(-15.5,5.5) U8(-14.5,5.5) U9(-13.5,5.5) U10(-12.5,5.5) U11(-11.5,5.5) U12(-10.5,5.5) U13(-9.5,5.5) U14(-8.5,5.5) U15(-7.5,5.5) U16(-6.5,5.5) U17(-5.5,5.5) U18(-4.5,5.5) U19(-3.5,5.5) U20(-2.5,5.5) U21(-1.5,5.5) U22(-0.5,5.5) U23(0.5,5.5) U24(1.5,5.5) U25(2.5,5.5) U26(3.5,5.5) U27(4.5,5.5) U28(5.5,5.5) U29(6.5,5.5) U30(7.5,5.5) U31(8.5,5.5) U32(9.5,5.5) U33(10.5,5.5) U34(11.5,5.5) U35(12.5,5.5) U36(13.5,5.5) U37(14.5,5.5) U38(15.5,5.5) U39(16.5,5.5) U40(17.5,5.5) U41(18.5,5.5) U42(19.5,5.5) U43(20.5,5.5) U44(21.5,5.5) V1(-21.5,4.5) V2(-20.5,4.5) V3(-19.5,4.5) V4(-18.5,4.5) V5(-17.5,4.5) V6(-16.5,4.5) V7(-15.5,4.5) V8(-14.5,4.5) V9(-13.5,4.5) V10(-12.5,4.5) V11(-11.5,4.5) V12(-10.5,4.5) V13(-9.5,4.5) V14(-8.5,4.5) V15(-7.5,4.5) V16(-6.5,4.5) V17(-5.5,4.5) V18(-4.5,4.5) V19(-3.5,4.5) V20(-2.5,4.5) V21(-1.5,4.5) V22(-0.5,4.5) V23(0.5,4.5) V24(1.5,4.5) V25(2.5,4.5) V26(3.5,4.5) V27(4.5,4.5) V28(5.5,4.5) V29(6.5,4.5) V30(7.5,4.5) V31(8.5,4.5) V32(9.5,4.5) V33(10.5,4.5) V34(11.5,4.5) V35(12.5,4.5) V36(13.5,4.5) V37(14.5,4.5) V38(15.5,4.5) V39(16.5,4.5) V40(17.5,4.5) V41(18.5,4.5) V42(19.5,4.5) V43(20.5,4.5) V44(21.5,4.5) W1(-21.5,3.5) W2(-20.5,3.5) W3(-19.5,3.5) W4(-18.5,3.5) W5(-17.5,3.5) W6(-16.5,3.5) W7(-15.5,3.5) W8(-14.5,3.5) W9(-13.5,3.5) W10(-12.5,3.5) W11(-11.5,3.5) W12(-10.5,3.5) W13(-9.5,3.5) W14(-8.5,3.5) W15(-7.5,3.5) W16(-6.5,3.5) W17(-5.5,3.5) W18(-4.5,3.5) W19(-3.5,3.5) W20(-2.5,3.5) W21(-1.5,3.5) W22(-0.5,3.5) W23(0.5,3.5) W24(1.5,3.5) W25(2.5,3.5) W26(3.5,3.5) W27(4.5,3.5) W28(5.5,3.5) W29(6.5,3.5) W30(7.5,3.5) W31(8.5,3.5) W32(9.5,3.5) W33(10.5,3.5) W34(11.5,3.5) W35(12.5,3.5) W36(13.5,3.5) W37(14.5,3.5) W38(15.5,3.5) W39(16.5,3.5) W40(17.5,3.5) W41(18.5,3.5) W42(19.5,3.5) W43(20.5,3.5) W44(21.5,3.5) Y1(-21.5,2.5) Y2(-20.5,2.5) Y3(-19.5,2.5) Y4(-18.5,2.5) Y5(-17.5,2.5) Y6(-16.5,2.5) Y7(-15.5,2.5) Y8(-14.5,2.5) Y9(-13.5,2.5) Y10(-12.5,2.5) Y11(-11.5,2.5) Y12(-10.5,2.5) Y13(-9.5,2.5) Y14(-8.5,2.5) Y15(-7.5,2.5) Y16(-6.5,2.5) Y17(-5.5,2.5) Y18(-4.5,2.5) Y19(-3.5,2.5) Y20(-2.5,2.5) Y21(-1.5,2.5) Y22(-0.5,2.5) Y23(0.5,2.5) Y24(1.5,2.5) Y25(2.5,2.5) Y26(3.5,2.5) Y27(4.5,2.5) Y28(5.5,2.5) Y29(6.5,2.5) Y30(7.5,2.5) Y31(8.5,2.5) Y32(9.5,2.5) Y33(10.5,2.5) Y34(11.5,2.5) Y35(12.5,2.5) Y36(13.5,2.5) Y37(14.5,2.5) Y38(15.5,2.5) Y39(16.5,2.5) Y40(17.5,2.5) Y41(18.5,2.5) Y42(19.5,2.5) Y43(20.5,2.5) Y44(21.5,2.5)
Top Overlay:
  circle w0.25: c-23.15,21.5 r0.125
  region: -21.5,22.5 -22.5,21.5 -22.5,22.5
  lines w0.2: -22.5,21.5 -21.5,22.5 ; -22.5,-22.5 -22.5,22.5 22.5,22.5 22.5,-22.5 -22.5,-22.5
Mechanical 13:
  lines w0.1: -22.5,-22.5 -22.5,22.5 22.5,22.5 22.5,-22.5 -22.5,-22.5
Mechanical 15:
  lines w0.1: -0.5,0 0.5,0 ; 0,-0.5 0,0.5 ; -23.5,-23.5 -23.5,23.5 23.5,23.5 23.5,-23.5 -23.5,-23.5
3D body: height 0, standoff 0, extent -22.5,-22.5 22.5,22.5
